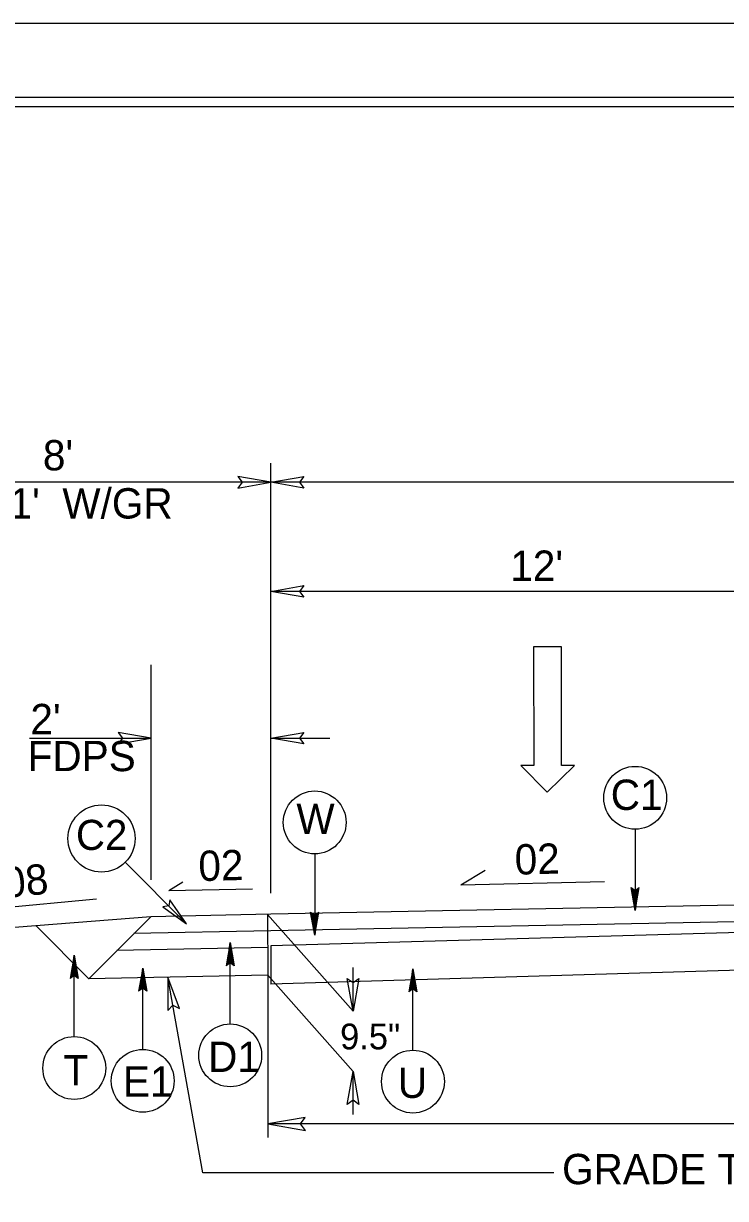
# Model space of a CAD drawing. Extents: x 2532463 to 2534146, y 189689 to 190784.
# Drawn here: x 2533260.3 to 2533450.3, y 190466.5 to 190784.2 of the extents above; entities that cross this region are included whole.
import ezdxf

# ---------------------------------------------------------------- set-up
doc = ezdxf.new("R2010")
doc.units = 0
for name, color, linetype in [('Old_Level_1', 7, 'Continuous'), ('Old_Level_11', 7, 'Continuous'), ('Old_Level_12', 7, 'Continuous'), ('Old_Level_18', 7, 'Continuous'), ('Old_Level_2', 7, 'Continuous'), ('Old_Level_3', 7, 'Continuous'), ('Old_Level_4', 7, 'Continuous'), ('Old_Level_50', 7, 'Continuous'), ('Old_Level_51', 7, 'Continuous'), ('Typical Bridge Rail CELL', 7, 'Continuous'), ('Typical Curb CELL', 7, 'Continuous'), ('Typical ID Circle CELL', 7, 'Continuous'), ('Typical Shoulder Slope Information CELL', 7, 'Continuous')]:
    doc.layers.add(name, color=color, linetype=linetype)

msp = doc.modelspace()

# ---------------------------------------------------------------- linework, layer by layer
at = {"layer": 'Old_Level_1'}
for p, q in [((2533425.83, 190544.33), (2533424.74, 190550.56)), ((2533424.74, 190550.56), (2533425.83, 190549.75)), ((2533424.89, 190550.45), (2533425.83, 190544.33)), ((2533425.83, 190544.33), (2533425.05, 190550.33)), ((2533425.21, 190550.21), (2533425.83, 190544.33)), ((2533425.83, 190544.33), (2533426.93, 190550.56)), ((2533425.83, 190549.75), (2533426.93, 190550.56)), ((2533425.83, 190544.33), (2533426.78, 190550.45)), ((2533426.62, 190550.33), (2533425.83, 190544.33)), ((2533425.83, 190544.33), (2533426.46, 190550.21)), ((2533425.83, 190544.33), (2533425.36, 190550.1)), ((2533425.52, 190549.99), (2533425.83, 190544.33)), ((2533425.83, 190544.33), (2533425.68, 190549.87)), ((2533426.31, 190550.1), (2533425.83, 190544.33)), ((2533425.83, 190544.33), (2533426.15, 190549.99)), ((2533425.99, 190549.87), (2533425.83, 190544.33)), ((2533425.83, 190549.75), (2533425.83, 190544.33)), ((2533463.59, 190546.03), (2533327.27, 190543.31)), ((2533339.12, 190537.67), (2533338.02, 190543.9)), ((2533338.02, 190543.9), (2533339.12, 190543.09)), ((2533338.18, 190543.79), (2533339.12, 190537.67)), ((2533339.12, 190537.67), (2533340.22, 190543.9)), ((2533339.12, 190543.09), (2533340.22, 190543.9)), ((2533339.12, 190537.67), (2533340.06, 190543.79)), ((2533294.8, 190542.66), (2533216.29, 190536.38)), ((2533294.8, 190542.66), (2533278.05, 190525.9)), ((2533327.27, 190543.31), (2533294.8, 190542.66)), ((2533326.32, 190543.29), (2533326.42, 190526.87)), ((2533463.59, 190541.52), (2533327.27, 190538.8)), ((2533339.12, 190537.67), (2533338.34, 190543.67)), ((2533338.49, 190543.55), (2533339.12, 190537.67)), ((2533339.12, 190537.67), (2533338.65, 190543.44)), ((2533338.8, 190543.33), (2533339.12, 190537.67)), ((2533339.12, 190537.67), (2533338.96, 190543.21)), ((2533339.91, 190543.67), (2533339.12, 190537.67)), ((2533339.12, 190537.67), (2533339.75, 190543.55)), ((2533339.59, 190543.44), (2533339.12, 190537.67)), ((2533339.12, 190537.67), (2533339.44, 190543.33)), ((2533339.28, 190543.21), (2533339.12, 190537.67)), ((2533339.12, 190543.09), (2533339.12, 190537.67)), ((2533263.78, 190540.18), (2533278.05, 190525.9)), ((2533327.27, 190538.83), (2533290.23, 190538.09)), ((2533463.67, 190538.69), (2533327.27, 190534.75)), ((2533326.42, 190534.3), (2533285.63, 190533.49)), ((2533316.27, 190535.64), (2533315.17, 190529.41)), ((2533316.27, 190535.64), (2533315.33, 190529.53)), ((2533315.48, 190529.65), (2533316.27, 190535.64)), ((2533316.27, 190535.64), (2533315.64, 190529.76)), ((2533315.8, 190529.88), (2533316.27, 190535.64)), ((2533316.27, 190535.64), (2533315.96, 190529.99)), ((2533316.11, 190530.1), (2533316.27, 190535.64)), ((2533316.27, 190535.64), (2533317.37, 190529.41)), ((2533317.21, 190529.53), (2533316.27, 190535.64)), ((2533316.27, 190535.64), (2533317.05, 190529.65)), ((2533316.9, 190529.76), (2533316.27, 190535.64)), ((2533316.27, 190535.64), (2533316.74, 190529.88)), ((2533316.59, 190529.99), (2533316.27, 190535.64)), ((2533316.27, 190535.64), (2533316.43, 190530.1)), ((2533316.27, 190530.22), (2533316.27, 190535.64)), ((2533327.27, 190534.75), (2533327.27, 190524.39)), ((2533274.07, 190532.22), (2533272.97, 190525.99)), ((2533274.07, 190532.22), (2533273.13, 190526.1)), ((2533273.28, 190526.22), (2533274.07, 190532.22)), ((2533274.07, 190532.22), (2533273.44, 190526.34)), ((2533273.6, 190526.45), (2533274.07, 190532.22)), ((2533274.07, 190532.22), (2533273.75, 190526.56)), ((2533273.91, 190526.68), (2533274.07, 190532.22)), ((2533274.07, 190532.22), (2533275.17, 190525.99)), ((2533275.01, 190526.1), (2533274.07, 190532.22)), ((2533274.07, 190532.22), (2533274.85, 190526.22)), ((2533274.7, 190526.34), (2533274.07, 190532.22)), ((2533274.07, 190532.22), (2533274.54, 190526.45)), ((2533274.38, 190526.56), (2533274.07, 190532.22)), ((2533274.07, 190532.22), (2533274.23, 190526.68)), ((2533274.07, 190526.8), (2533274.07, 190532.22)), ((2533292.59, 190528.75), (2533291.49, 190522.52)), ((2533292.59, 190528.75), (2533291.65, 190522.63)), ((2533291.8, 190522.75), (2533292.59, 190528.75)), ((2533292.59, 190528.75), (2533291.96, 190522.87)), ((2533292.12, 190522.98), (2533292.59, 190528.75)), ((2533292.59, 190528.75), (2533292.28, 190523.09)), ((2533292.43, 190523.21), (2533292.59, 190528.75)), ((2533292.59, 190528.75), (2533293.69, 190522.52)), ((2533293.53, 190522.63), (2533292.59, 190528.75)), ((2533292.59, 190528.75), (2533293.37, 190522.75)), ((2533293.22, 190522.87), (2533292.59, 190528.75)), ((2533292.59, 190528.75), (2533293.06, 190522.98)), ((2533292.91, 190523.09), (2533292.59, 190528.75)), ((2533292.59, 190528.75), (2533292.75, 190523.21)), ((2533292.59, 190523.33), (2533292.59, 190528.75)), ((2533316.27, 190530.22), (2533315.17, 190529.41)), ((2533317.37, 190529.41), (2533316.27, 190530.22)), ((2533463.28, 190528.44), (2533327.27, 190524.39)), ((2533365.7, 190528.54), (2533364.6, 190522.31)), ((2533365.7, 190528.54), (2533364.75, 190522.42)), ((2533364.91, 190522.54), (2533365.7, 190528.54)), ((2533365.7, 190528.54), (2533365.07, 190522.66)), ((2533365.23, 190522.77), (2533365.7, 190528.54)), ((2533365.7, 190528.54), (2533365.38, 190522.88)), ((2533365.54, 190523), (2533365.7, 190528.54)), ((2533365.7, 190528.54), (2533366.8, 190522.31)), ((2533366.64, 190522.42), (2533365.7, 190528.54)), ((2533365.7, 190528.54), (2533366.48, 190522.54)), ((2533366.33, 190522.66), (2533365.7, 190528.54)), ((2533365.7, 190528.54), (2533366.17, 190522.77)), ((2533366.01, 190522.88), (2533365.7, 190528.54)), ((2533365.7, 190528.54), (2533365.86, 190523)), ((2533365.7, 190523.12), (2533365.7, 190528.54)), ((2533274.07, 190526.8), (2533272.97, 190525.99)), ((2533275.17, 190525.99), (2533274.07, 190526.8)), ((2533326.42, 190526.87), (2533278.05, 190525.9)), ((2533292.59, 190523.33), (2533291.49, 190522.52)), ((2533293.69, 190522.52), (2533292.59, 190523.33)), ((2533365.7, 190523.12), (2533364.6, 190522.31)), ((2533366.8, 190522.31), (2533365.7, 190523.12))]:
    msp.add_line(p, q, dxfattribs=at)
at = {"layer": 'Old_Level_11'}
msp.add_lwpolyline([(2533336.55, 190488.37), (2533326.42, 190486.63), (2533336.6, 190484.83), (2533335.31, 190486.63)], close=True, dxfattribs=at)
at = {"layer": 'Old_Level_18'}
msp.add_lwpolyline([(2534129.31, 190761.68), (2532629.31, 190761.68), (2532629.31, 189711.68), (2534129.31, 189711.68)], close=True, dxfattribs=at)
at = {"layer": 'Old_Level_2'}
for p, q in [((2533327.27, 190549), (2533327.27, 190665.28)), ((2533327.27, 190660.13), (2533216.33, 190660.13)), ((2533463.59, 190660.13), (2533327.27, 190660.13)), ((2533463.59, 190630.63), (2533327.27, 190630.63)), ((2533294.87, 190552.63), (2533294.87, 190610.73)), ((2533262, 190590.93), (2533294.87, 190590.93)), ((2533327.27, 190590.93), (2533343.26, 190590.93)), ((2533425.83, 190566.31), (2533425.83, 190544.33)), ((2533339.12, 190559.64), (2533339.12, 190537.67)), ((2533378.69, 190551.29), (2533385.2, 190555.26)), ((2533378.69, 190551.29), (2533417.54, 190552.2)), ((2533241.37, 190543.9), (2533280.07, 190547.5)), ((2533349.49, 190517.08), (2533326.32, 190543.29)), ((2533316.27, 190513.67), (2533316.27, 190535.64)), ((2533274.07, 190510.25), (2533274.07, 190532.22)), ((2533292.59, 190506.78), (2533292.59, 190528.75)), ((2533349.49, 190517.08), (2533349.49, 190528.91)), ((2533365.7, 190506.57), (2533365.7, 190528.54)), ((2533308.84, 190473.41), (2533299.4, 190526.33)), ((2533326.42, 190526.87), (2533326.42, 190482.99)), ((2533349.49, 190500.78), (2533326.42, 190526.87)), ((2533349.49, 190489.21), (2533349.49, 190500.78)), ((2533463.59, 190486.63), (2533326.42, 190486.63)), ((2533403.86, 190473.41), (2533308.84, 190473.41))]:
    msp.add_line(p, q, dxfattribs=at)
for centre in [(2533425.83, 190574.81), (2533339.12, 190568.15), (2533316.27, 190505.16), (2533274.07, 190501.74), (2533292.59, 190498.27), (2533365.7, 190498.06)]:
    msp.add_circle(centre, 8.5, dxfattribs=at)
at = {"layer": 'Old_Level_3'}
for p, q in [((2533327.27, 190660.13), (2533318.37, 190661.7)), ((2533318.37, 190661.7), (2533319.53, 190660.13)), ((2533327.27, 190660.13), (2533336.18, 190661.7)), ((2533336.18, 190661.7), (2533335.02, 190660.13)), ((2533318.37, 190658.56), (2533327.27, 190660.13)), ((2533319.53, 190660.13), (2533318.37, 190658.56)), ((2533336.18, 190658.56), (2533327.27, 190660.13)), ((2533335.02, 190660.13), (2533336.18, 190658.56)), ((2533327.27, 190630.63), (2533336.18, 190632.2)), ((2533336.18, 190629.06), (2533327.27, 190630.63)), ((2533336.18, 190632.2), (2533335.02, 190630.63)), ((2533335.02, 190630.63), (2533336.18, 190629.06)), ((2533294.87, 190590.93), (2533285.97, 190592.5)), ((2533285.97, 190592.5), (2533287.13, 190590.93)), ((2533327.27, 190590.93), (2533336.18, 190592.5)), ((2533336.18, 190592.5), (2533335.02, 190590.93)), ((2533285.97, 190589.36), (2533294.87, 190590.93)), ((2533287.13, 190590.93), (2533285.97, 190589.36)), ((2533336.18, 190589.36), (2533327.27, 190590.93)), ((2533335.02, 190590.93), (2533336.18, 190589.36)), ((2533302.51, 190517.84), (2533299.4, 190526.33)), ((2533299.4, 190526.33), (2533299.41, 190517.29)), ((2533349.49, 190517.08), (2533347.92, 190525.99)), ((2533347.92, 190525.99), (2533349.49, 190524.83)), ((2533351.06, 190525.99), (2533349.49, 190517.08)), ((2533349.49, 190524.83), (2533351.06, 190525.99)), ((2533299.41, 190517.29), (2533300.76, 190518.71)), ((2533300.76, 190518.71), (2533302.51, 190517.84)), ((2533347.92, 190491.87), (2533349.49, 190500.78)), ((2533349.49, 190500.78), (2533351.06, 190491.87)), ((2533349.49, 190493.03), (2533347.92, 190491.87)), ((2533351.06, 190491.87), (2533349.49, 190493.03))]:
    msp.add_line(p, q, dxfattribs=at)
at = {"layer": 'Old_Level_4'}
for p, q in [((2533405.93, 190615.66), (2533398.36, 190615.65)), ((2533398.36, 190615.65), (2533398.37, 190583.52)), ((2533405.94, 190583.53), (2533405.93, 190615.66)), ((2533398.37, 190583.52), (2533394.93, 190583.52)), ((2533394.93, 190583.52), (2533402.04, 190576.29)), ((2533402.04, 190576.29), (2533409.38, 190583.53)), ((2533409.38, 190583.53), (2533405.94, 190583.53))]:
    msp.add_line(p, q, dxfattribs=at)
at = {"layer": 'Old_Level_50'}
msp.add_lwpolyline([(2532475.81, 189709.18), (2534141.81, 189709.18), (2534141.81, 190764.18), (2532475.81, 190764.18)], close=True, dxfattribs=at)
at = {"layer": 'Old_Level_51'}
msp.add_lwpolyline([(2532462.81, 189689.18), (2534146.31, 189689.18), (2534146.31, 190784.18), (2532462.81, 190784.18)], close=True, dxfattribs=at)
at = {"layer": 'Typical Bridge Rail CELL'}
msp.add_line((2533287.87, 190557.37), (2533304.48, 190540.76), dxfattribs=at)
msp.add_circle((2533281.45, 190563.8), 9.09, dxfattribs=at)
at = {"layer": 'Typical Curb CELL'}
for q in [(2533303.45, 190552.05), (2533322.3, 190550.2)]:
    msp.add_line((2533299.65, 190549.75), q, dxfattribs=at)
at = {"layer": 'Typical ID Circle CELL'}
msp.add_lwpolyline([(2533298.06, 190545.3), (2533304.48, 190540.76), (2533299.94, 190547.25), (2533299.67, 190545.57)], close=True, dxfattribs=at)

# ---------------------------------------------------------------- texts
at = {"layer": 'Old_Level_12'}
for s, height, rotation, p in [("12'", 8.201, 359.9999, (2533392.04, 190633.47)), ('C1', 8.201, 359.9999, (2533419.22, 190571.53)), ('W', 8.2, 359.9999, (2533334.17, 190565.02)), ('D1', 8.201, 359.9999, (2533310.28, 190500.68)), ('T', 8.2, 359.9999, (2533271.17, 190497.02)), ('E1', 8.201, 359.9999, (2533287.23, 190494.03)), ('U', 8.2, 359.9999, (2533361.62, 190493.65)), ('GRADE TO THIS LINE', 8.2009, 0.0001, (2533406.05, 190470.32))]:
    msp.add_text(s, height=height, rotation=rotation, dxfattribs=at).set_placement(p)
at = {"layer": 'Old_Level_2'}
for s, height, rotation, p in [("8'", 8.201, 359.9999, (2533265.58, 190663.34)), ("11'  W/GR", 8.201, 359.9999, (2533250.46, 190650.33)), ("2'", 8.201, 359.9999, (2533262.21, 190592)), ('FDPS', 8.201, 359.9999, (2533261.46, 190582.01)), ('.08', 8.201, 5.8332, (2533252.19, 190547.38)), ('9.5"', 6.971, 0.0462, (2533346, 190506.78))]:
    msp.add_text(s, height=height, rotation=rotation, dxfattribs=at).set_placement(p)
at = {"layer": 'Old_Level_3'}
for p in [(2533307.76, 190552.26), (2533393.34, 190554)]:
    msp.add_text('02', height=8.201, rotation=1.5465, dxfattribs=at).set_placement(p)
at = {"layer": 'Typical Shoulder Slope Information CELL'}
msp.add_text('C2', height=8.135, dxfattribs=at).set_placement((2533274.53, 190560.71))

doc.saveas('drawing.dxf')
